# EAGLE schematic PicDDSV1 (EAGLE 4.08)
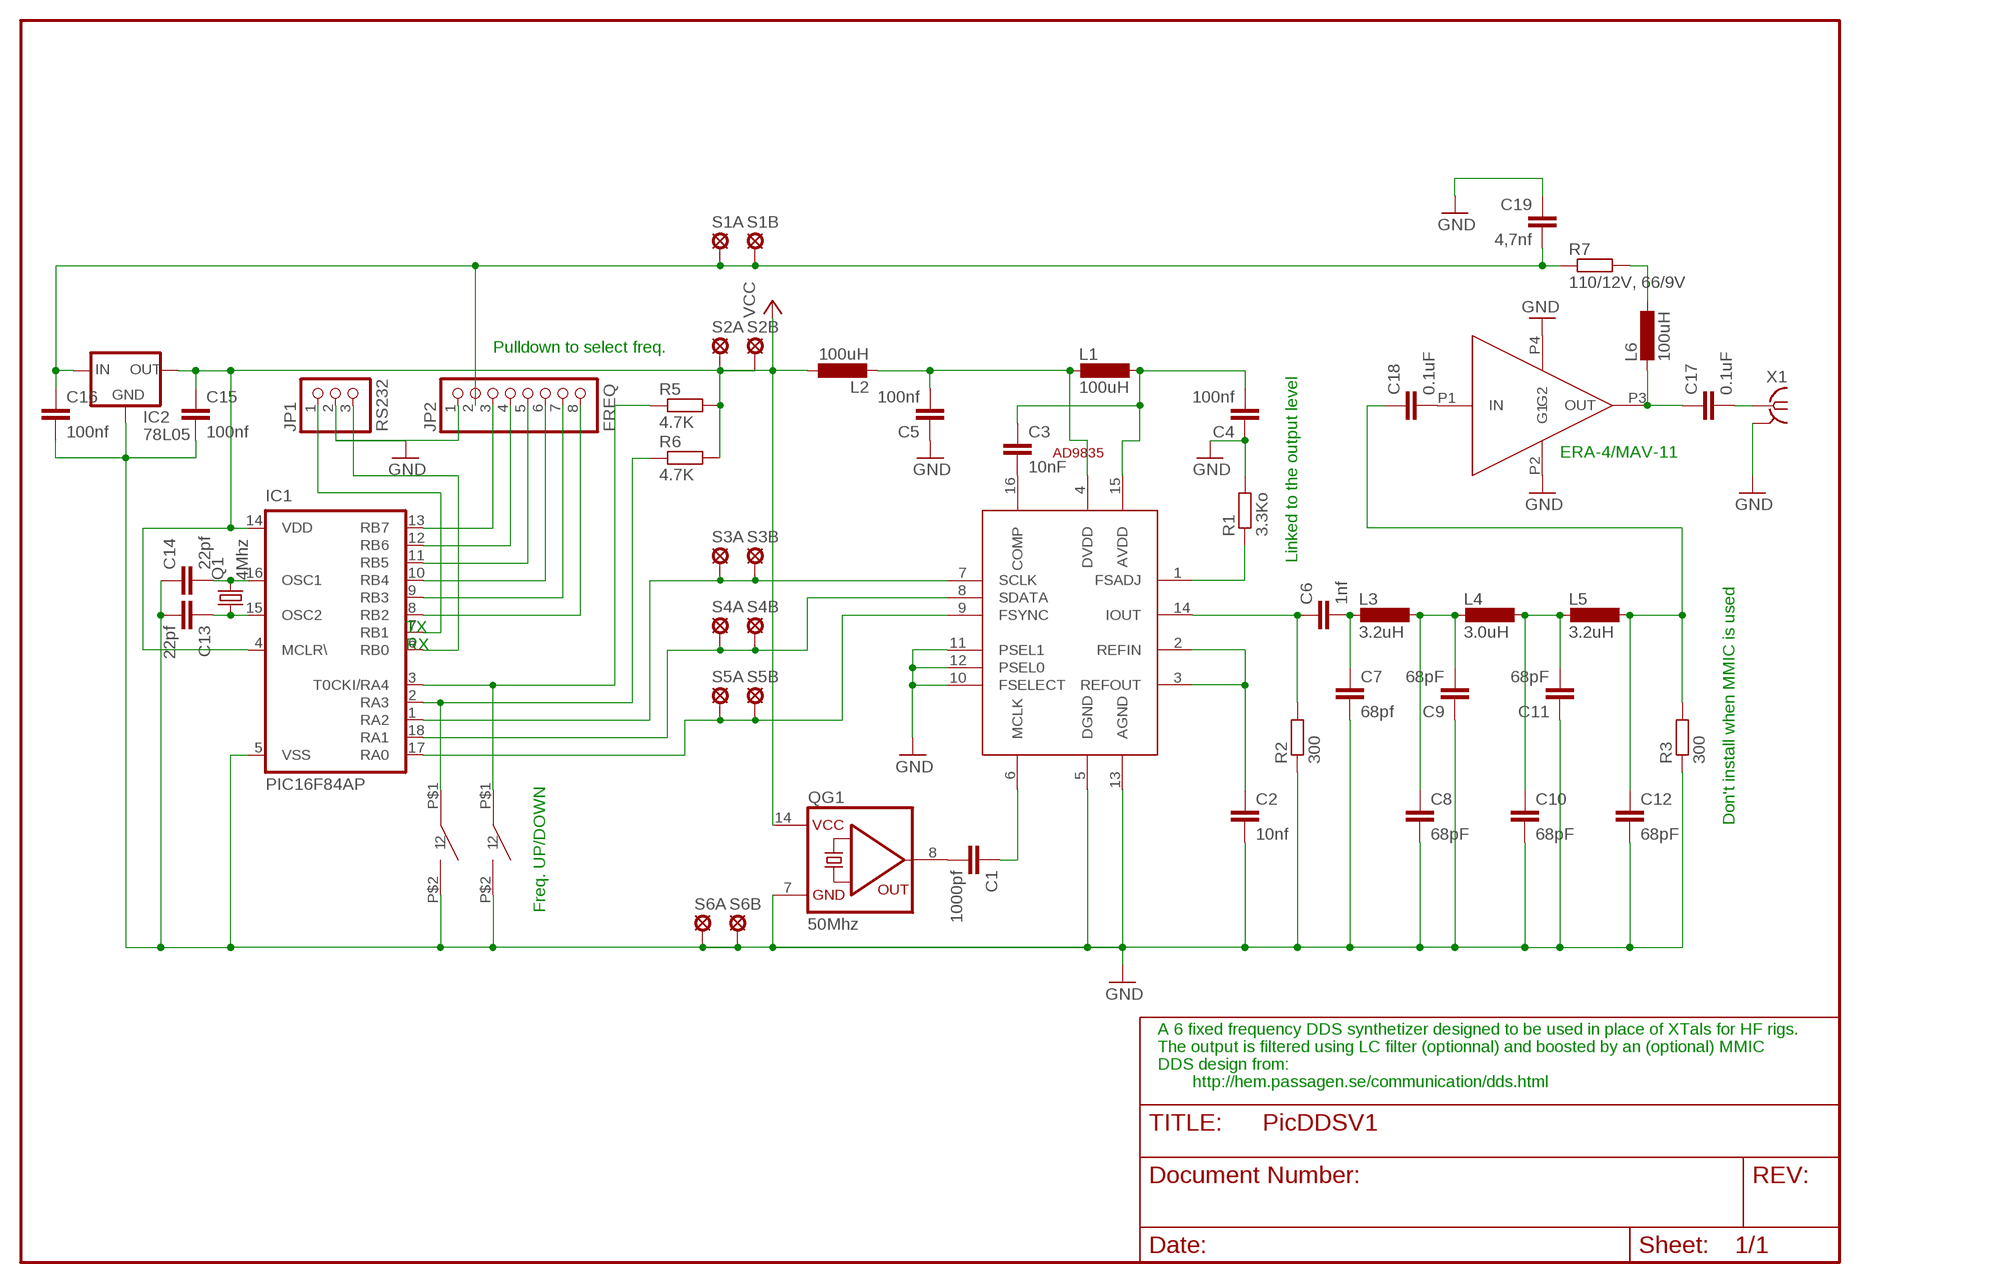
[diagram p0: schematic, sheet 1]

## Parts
BP1  BUTTON1  [PBUTTON]
BP2  BUTTON1  [PBUTTON]
C1  1000pf  C-EU025-025X050  [C025-025X050]
C2  10nf  C-EU025-025X050  [C025-025X050]
C3  10nF  C-EU050-030X075  [C050-030X075]
C4  100nf  C-EU050-025X075  [C050-025X075]
C5  100nf  C-EU050-025X075  [C050-025X075]
C6  1nf  C-EU025-024X044  [C025-024X044]
C7  68pf  C-EU025-024X044  [C025-024X044]
C8  68pF  C-EU025-024X044  [C025-024X044]
C9  68pF  C-EU025-024X044  [C025-024X044]
C10  68pF  C-EU025-024X044  [C025-024X044]
C11  68pF  C-EU025-024X044  [C025-024X044]
C12  68pF  C-EU025-024X044  [C025-024X044]
C13  22pf  C-EU025-024X044  [C025-024X044]
C14  22pf  C-EU025-024X044  [C025-024X044]
C15  100nf  C-EU025-030X050  [C025-030X050]
C16  100nf  C-EU025-030X050  [C025-030X050]
C17  0.1uF  C-EU025-024X044  [C025-024X044]
C18  0.1uF  C-EU025-024X044  [C025-024X044]
C19  4,7nf  C-EU025-024X044  [C025-024X044]
IC1  PIC16F84AP  [DIL18]
IC2  78L05  78LXX  [78LXX]
JP1  RS232  PINHD-1X3  [1X03]
JP2  FREQ  PINHD-1X8  [1X08]
L1  100uH  L-EU0207/7  [0207/7]
L2  100uH  L-EU0207/7  [0207/7]
L3  3.2uH  L-EU0207/7  [0207/7]
L4  3.0uH  L-EU0207/7  [0207/7]
L5  3.2uH  L-EU0207/7  [0207/7]
L6  100uH  L-EU0207/2V  [0207/2V]
M1  ERA  [PMMIC]
Q1  4Mhz  CRYTALHC49U-V  [HC49U-V]
QG1  50Mhz  QG5860  [DIL14S]
R1  3.3Ko  R-EU_0207/2V  [0207/2V]
R2  300  R-EU_0207/2V  [0207/2V]
R3  300  R-EU_0207/2V  [0207/2V]
R5  4.7K  R-EU_0207/2V  [0207/2V]
R6  4.7K  R-EU_0207/2V  [0207/2V]
R7  110/12V, 66/9V  R-EU_0207/2V  [0207/2V]
S1A  SE11  [SE11]
S1B  SE11  [SE11]
S2A  SE11  [SE11]
S2B  SE11  [SE11]
S3A  SE11  [SE11]
S3B  SE11  [SE11]
S4A  SE11  [SE11]
S4B  SE11  [SE11]
S5A  SE11  [SE11]
S5B  SE11  [SE11]
S6A  SE11  [SE11]
S6B  SE11  [SE11]
U$1  AD9835  [TSSOP]
X1  BU-SMA-V  [BU-SMA-V]

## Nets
GND: BP1.P$2 BP2.P$2 C2.2 C4.1 C5.1 C7.2 C8.2 C9.1 C10.2 C11.1 C12.2 C13.2 C14.1 C15.2 C16.2 C19.1 IC1.5(VSS) IC2.GND JP1.2 JP2.1 M1.P2(G1) M1.P4(G2) QG1.7(GND) R1.2 R2.1 R3.1 S6A.MP S6B.MP U$1.5(DGND) U$1.10(FSELECT) U$1.11(PSEL1) U$1.12(PSEL0) U$1.13(AGND) X1.2(GND)
N$1: C17.1 L6.2 M1.P3(OUT)
N$2: IC1.17(RA0) S5A.MP S5B.MP U$1.9(FSYNC)
N$3: C14.2 IC1.16(OSC1) Q1.2
N$4: C2.1 U$1.2(REFIN) U$1.3(REFOUT)
N$5: C1.1 U$1.6(MCLK)
N$6: C1.2 QG1.8(OUT)
N$7: C13.1 IC1.15(OSC2) Q1.1
N$8: R1.1 U$1.1(FSADJ)
N$9: C5.2 L1.2 L2.2 U$1.4(DVDD)
N$10: C6.1 R2.2 U$1.14(IOUT)
N$11: C18.2 M1.P1(IN)
N$12: C6.2 C7.1 L3.2
N$13: C8.1 C9.2 L3.1 L4.2
N$14: C10.1 C11.2 L4.1 L5.2
N$15: C12.1 C18.1 L5.1 R3.2
N$16: IC1.1(RA2) S3A.MP S3B.MP U$1.7(SCLK)
N$17: IC1.7(RB1) JP1.1
N$18: IC1.6(RB0) JP1.3
N$19: C3.2 U$1.16(COMP)
N$20: IC1.18(RA1) S4A.MP S4B.MP U$1.8(SDATA)
N$21: BP2.P$1 IC1.3(T0CKI/RA4) R5.1
N$22: BP1.P$1 IC1.2(RA3) R6.1
N$23: IC1.13(RB7) JP2.3
N$24: IC1.12(RB6) JP2.4
N$25: IC1.11(RB5) JP2.5
N$26: IC1.10(RB4) JP2.6
N$27: IC1.9(RB3) JP2.7
N$28: IC1.8(RB2) JP2.8
N$29: C3.1 C4.2 L1.1 U$1.15(AVDD)
N$32: C17.2 X1.1
N$34: L6.1 R7.2
N$36: C16.1 C19.2 IC2.IN JP2.2 R7.1 S1A.MP S1B.MP
VCC: C15.1 IC1.4(MCLR\) IC1.14(VDD) IC2.OUT L2.1 QG1.14(VCC) R5.2 R6.2 S2A.MP S2B.MP

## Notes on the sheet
- Pulldown to select freq.
- ERA-4/MAV-11
- Linked to the output level
- TX
- RX
- Don't install when MMIC is used
- Freq. UP/DOWN
- A 6 fixed frequency DDS synthetizer designed to be used in place of XTals for HF rigs.
- The output is filtered using LC filter (optionnal) and boosted by an (optional) MMIC
- DDS design from:
- http://hem.passagen.se/communication/dds.html

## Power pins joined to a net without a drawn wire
GND: X1.3(GND) X1.4(GND) X1.5(GND)

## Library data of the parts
BP1 BP2 = Button:BUTTON1
C1-C19 = rcl:C-EU: CAPACITOR, European symbol
IC1 = microchip:PIC16F8*: MICROCONTROLLER 8-Bit PIC16F8X Family - CMOS Flash/EEPROM Pin Compatible : PIC16F83, PIC16CR83, PIC16F84A, PIC16CR84 see also PIC16C*
IC2 = v-reg:78LXX: VOLTAGE REGULATOR
JP1 = pinhead:PINHD-1X3: PIN HEADER
JP2 = pinhead:PINHD-1X8: PIN HEADER
L1-L6 = rcl:L-EU: INDUCTOR, European symbol
M1 = Mmic:ERA
Q1 = crystal:CRYTAL: CRYSTAL
QG1 = crystal:QG5860: CRYSTAL RESONATOR
R1-R3 R5-R7 = rcl:R-EU_: RESISTOR, European symbol
S1A S1B S2A S2B S3A S3B S4A S4B S5A S5B S6A S6B = solpad:SE11: SOLDER PAD
U$1 = ad9835:AD9835: AD9835 - Copper side (bottom)
X1 = con-coax:BU-SMA-V: FEMALE SMA CONNECTOR Radiall distributor RS 112-3794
